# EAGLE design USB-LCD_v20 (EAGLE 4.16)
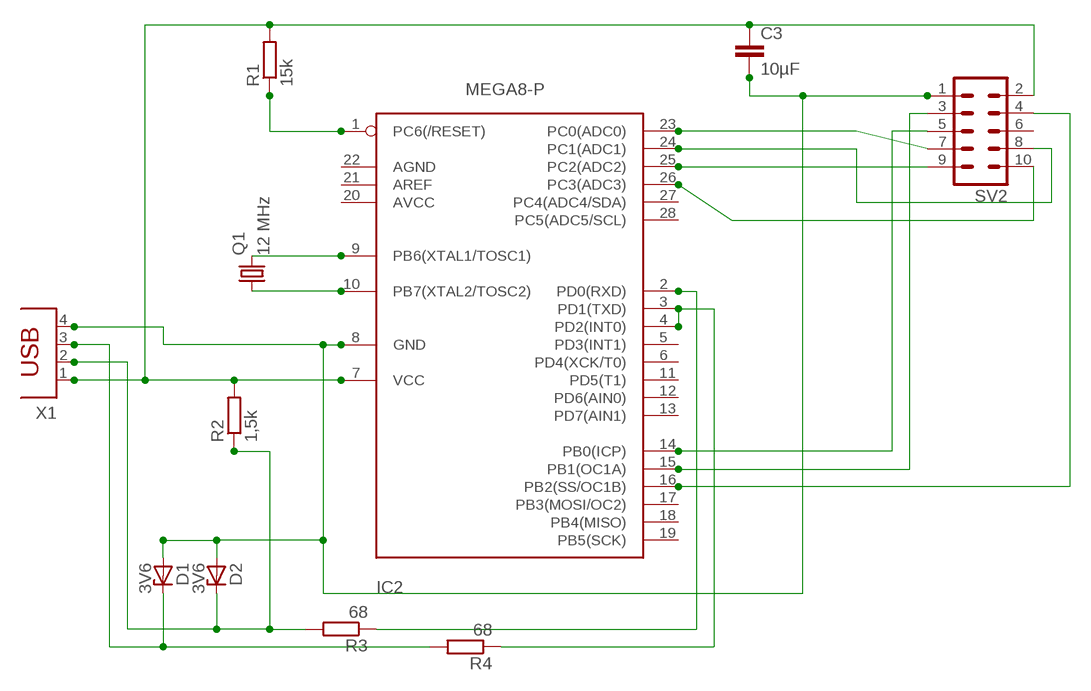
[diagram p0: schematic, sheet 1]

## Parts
C3  10µF  C2.5/6  [C2.5-6]
D1  3V6  ZENER-DIODEDO34-7  [DO34Z7]
D2  3V6  ZENER-DIODEDO34-7  [DO34Z7]
IC2  MEGA8-P  [DIL28-3]
Q1  12 MHz  CRYSTALHC49S  [HC49/S]
R1  15k  R-EU_0207/10  [0207/10]
R2  1,5k  R-EU_0207/10  [0207/10]
R3  68  R-EU_0207/10  [0207/10]
R4  68  R-EU_0207/10  [0207/10]
SV2  ML10  [ML10]
X1  PN61729  [PN61729]

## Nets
N$1: D1.C R4.2 X1.3
N$2: D2.C R2.1 R3.2 X1.2
N$3: IC2.16(PB2(SS/OC1B)) SV2.4
N$4: C3.2 D1.A D2.A IC2.8(GND) SV2.1 X1.4
N$5: IC2.9(PB6(XTAL1/TOSC1)) Q1.2
N$6: IC2.10(PB7(XTAL2/TOSC2)) Q1.1
N$7: C3.1 IC2.7(VCC) R1.2 R2.2 SV2.2 X1.1
N$8: IC2.15(PB1(OC1A)) SV2.3
N$9: IC2.14(PB0(ICP)) SV2.5
N$10: IC2.24(PC1(ADC1)) SV2.8
N$11: IC2.23(PC0(ADC0)) SV2.7
N$12: IC2.25(PC2(ADC2)) SV2.9
N$13: IC2.26(PC3(ADC3)) SV2.10
N$14: IC2.2(PD0(RXD)) R3.1
N$15: IC2.3(PD1(TXD)) IC2.4(PD2(INT0)) R4.1
N$16: IC2.1(PC6(/RESET)) R1.1
Unconnected: IC2.5(PD3(INT1)) IC2.6(PD4(XCK/T0)) IC2.11(PD5(T1)) IC2.12(PD6(AIN0)) IC2.13(PD7(AIN1)) IC2.17(PB3(MOSI/OC2)) IC2.18(PB4(MISO)) IC2.19(PB5(SCK)) IC2.20(AVCC) IC2.21(AREF) IC2.22(AGND) IC2.27(PC4(ADC4/SDA)) IC2.28(PC5(ADC5/SCL)) SV2.6

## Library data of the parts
C3 = capacitor-wima:C: CAPACITOR
D1 D2 = diode:ZENER-DIODE: Z-Diode
IC2 = atmel:MEGA8-P: MICROCONTROLLER 8 Kbytes FLASH 1 kbytes SRAM 512 bytes EEPROM USART 4-channel 10 bit ADC 2-channel 8 bit ADC
Q1 = crystal:CRYSTAL: CRYSTAL
R1-R4 = rcl:R-EU_: RESISTOR, European symbol
SV2 = con-harting-ml:ML10: HARTING
X1 = con-berg:PN61729: BERG USB connector

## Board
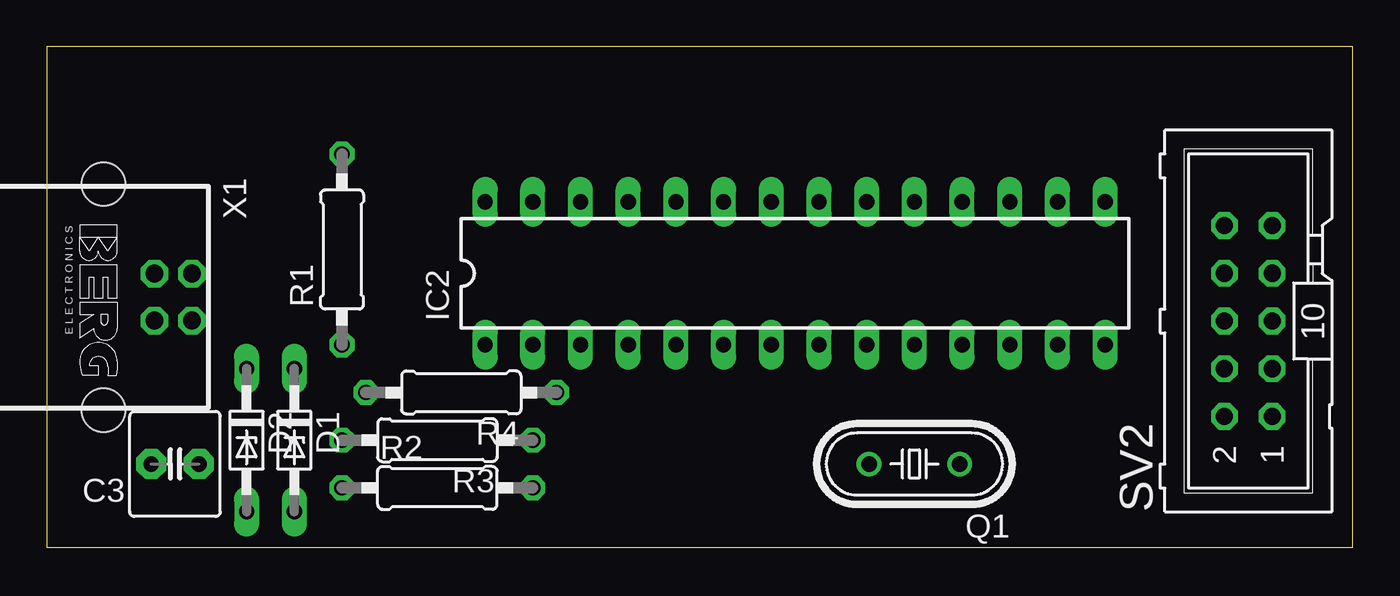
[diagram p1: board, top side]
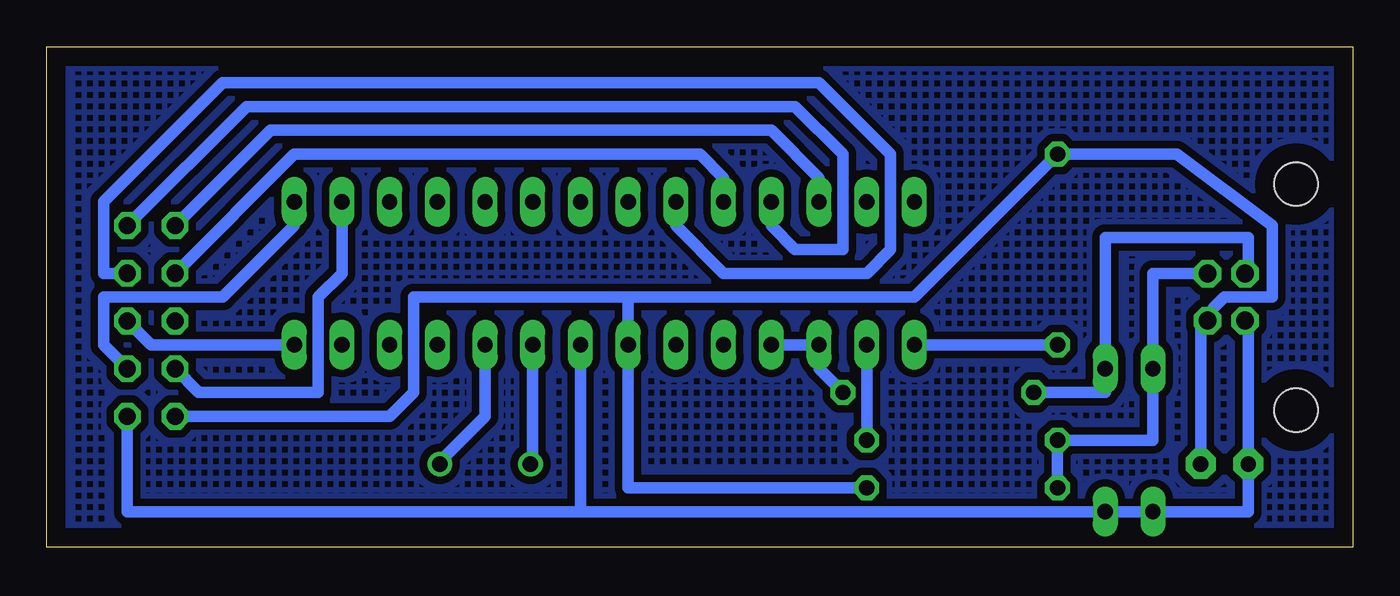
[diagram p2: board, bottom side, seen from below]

Size 69.52 x 26.66 mm. Coordinates in mm from the lower left corner, seen from the top.
Outline: 0,0 69.52,0 69.52,26.66 0,26.66 0,0
Copper layers (1*16): Top 0.035mm / dielectric 1.5mm / Bottom 0.035mm
Design rules "default": minimum track width 10mil, minimum drill 24mil, track to track 8mil, track to pad 8mil, pad to pad 8mil, via to via 8mil, smd to smd 8mil, copper to edge 40mil, drill to drill 8mil, minimum pad ring 10mil, minimum via ring 8mil, stop-mask expansion 4mil, vias tented up to drill 0mil, thermal gap 10mil

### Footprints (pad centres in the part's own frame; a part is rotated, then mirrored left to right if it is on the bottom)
C2.5-6 = drill 0.813 pad 1.6 octagon: 1 -1.27,0; 2 1.27,0
DO34Z7 = drill 0.813 long: A 3.81,0; C -3.81,0
DIL28-3 = drill 0.813 long: 1 -16.51,-3.81; 2 -13.97,-3.81; 3 -11.43,-3.81; 4 -8.89,-3.81; 5 -6.35,-3.81; 6 -3.81,-3.81; 7 -1.27,-3.81; 8 1.27,-3.81; 9 3.81,-3.81; 10 6.35,-3.81; 11 8.89,-3.81; 12 11.43,-3.81; 13 13.97,-3.81; 14 16.51,-3.81; 15 16.51,3.81; 16 13.97,3.81; 17 11.43,3.81; 18 8.89,3.81; 19 6.35,3.81; 20 3.81,3.81; 21 1.27,3.81; 22 -1.27,3.81; 23 -3.81,3.81; 24 -6.35,3.81; 25 -8.89,3.81; 26 -11.43,3.81; 27 -13.97,3.81; 28 -16.51,3.81
HC49/S = drill 0.813 round: 1 -2.413,0; 2 2.413,0
0207/10 = drill 0.813 octagon: 1 -5.08,0; 2 5.08,0
ML10 = drill 0.914 octagon: 1 -5.08,-1.27; 2 -5.08,1.27; 3 -2.54,-1.27; 4 -2.54,1.27; 5 0,-1.27; 6 0,1.27; 7 2.54,-1.27; 8 2.54,1.27; 9 5.08,-1.27; 10 5.08,1.27
PN61729 = drill 0.95 octagon: 1 1.25,4.71; 2 -1.25,4.71; 3 -1.25,2.71; 4 1.25,2.71 | hole 2.3: -6.02,0; 6.02,0

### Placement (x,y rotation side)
C3  6.82,4.44 180 top
D1  13.17,5.71 270 top
D2  10.63,5.71 270 top
IC2  39.84,14.6 0 top
Q1  46.19,4.44 180 top
R1  15.71,15.87 90 top
R2  20.79,3.17 0 top
R3  20.79,5.71 180 top
R4  22.06,8.25 180 top
SV2  63.97,12.06 90 top
X1  3.01,13.33 270 top

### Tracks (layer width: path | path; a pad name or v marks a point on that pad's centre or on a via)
GND
  pour Bottom (isolate 0.406, hatched): -0.8,27.3 70.32,27.3 70.32,-0.64 -0.8,-0.64
N$1
  Bottom 0.305: 5.6,14.58 arc-45 5.55,14.6
  Bottom 0.61: R4.2 13.17,8.25 D1.C 13.17,16.5 5.55,16.5 5.55,14.6 | X1.3 5.6,14.58
N$2
  Bottom 0.305: 10.63,14.6 arc-45 10.58,14.58
  Bottom 0.61: R2.1 R3.2 10.63,5.71 D2.C 10.63,14.6 | 10.58,14.58 X1.2
N$3
  Bottom 0.61: SV2.4 61.43,8.25 55.08,8.25 55.08,13.33 53.81,14.6 IC2.16
N$4
  Bottom 0.254: 5.55,12.06 X1.4
  Bottom 0.61: 5.55,12.06 C3.2 5.55,1.9 D1.A D2.A 41.11,1.9 | 41.11,1.9 IC2.8 | SV2.1 65.24,1.9 41.11,1.9
N$5
  Bottom 0.254: Q1.2 43.65,4.44
  Bottom 0.61: 43.65,4.44 IC2.9
N$6
  Bottom 0.254: Q1.1 48.73,4.44
  Bottom 0.61: 48.73,4.44 46.19,6.98 IC2.10
N$7
  Bottom 0.254: 38.57,12.06 IC2.7 | 8.09,12.06 X1.1
  Bottom 0.61: C3.1 8.09,12.06 6.82,13.33 4.28,13.33 4.28,17.14 9.36,20.95 R1.2 23.33,13.33 38.57,13.33 | R2.2 38.57,3.17 IC2.7 | 38.57,13.33 38.57,12.06 | SV2.2 51.27,6.98 50,8.25 50,13.33 38.57,13.33
N$8
  Bottom 0.61: SV2.3 66.51,10.79 66.51,13.33 60.16,13.33 56.35,17.14 IC2.15
N$9
  Bottom 0.61: IC2.14 63.97,10.79 SV2.5
N$10
  Bottom 0.61: SV2.8 56.35,20.95 34.76,20.95 33.49,19.68 IC2.24
N$11
  Bottom 0.61: SV2.7 66.51,14.6 66.51,18.41 60.16,24.76 28.41,24.76 24.6,20.95 24.6,15.87 25.87,14.6 33.49,14.6 36.03,17.14 IC2.23
N$12
  Bottom 0.61: SV2.9 58.89,23.49 29.68,23.49 27.14,20.95 27.14,15.87 29.68,15.87 30.95,17.14 IC2.25
N$13
  Bottom 0.61: SV2.10 57.62,22.22 30.95,22.22 28.41,19.68 IC2.26
N$14
  Bottom 0.61: R3.1 IC2.2
N$15
  Bottom 0.61: R4.1 28.41,9.52 IC2.3 IC2.4
N$16
  Bottom 0.61: R1.1 IC2.1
